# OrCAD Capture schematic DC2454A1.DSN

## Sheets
1 PAGE2: size Custom; title: POLY-PHASE DC/DC CONVERTER WITH POWER SYSTEM MANAGEMENT; rev: 1; company: TM
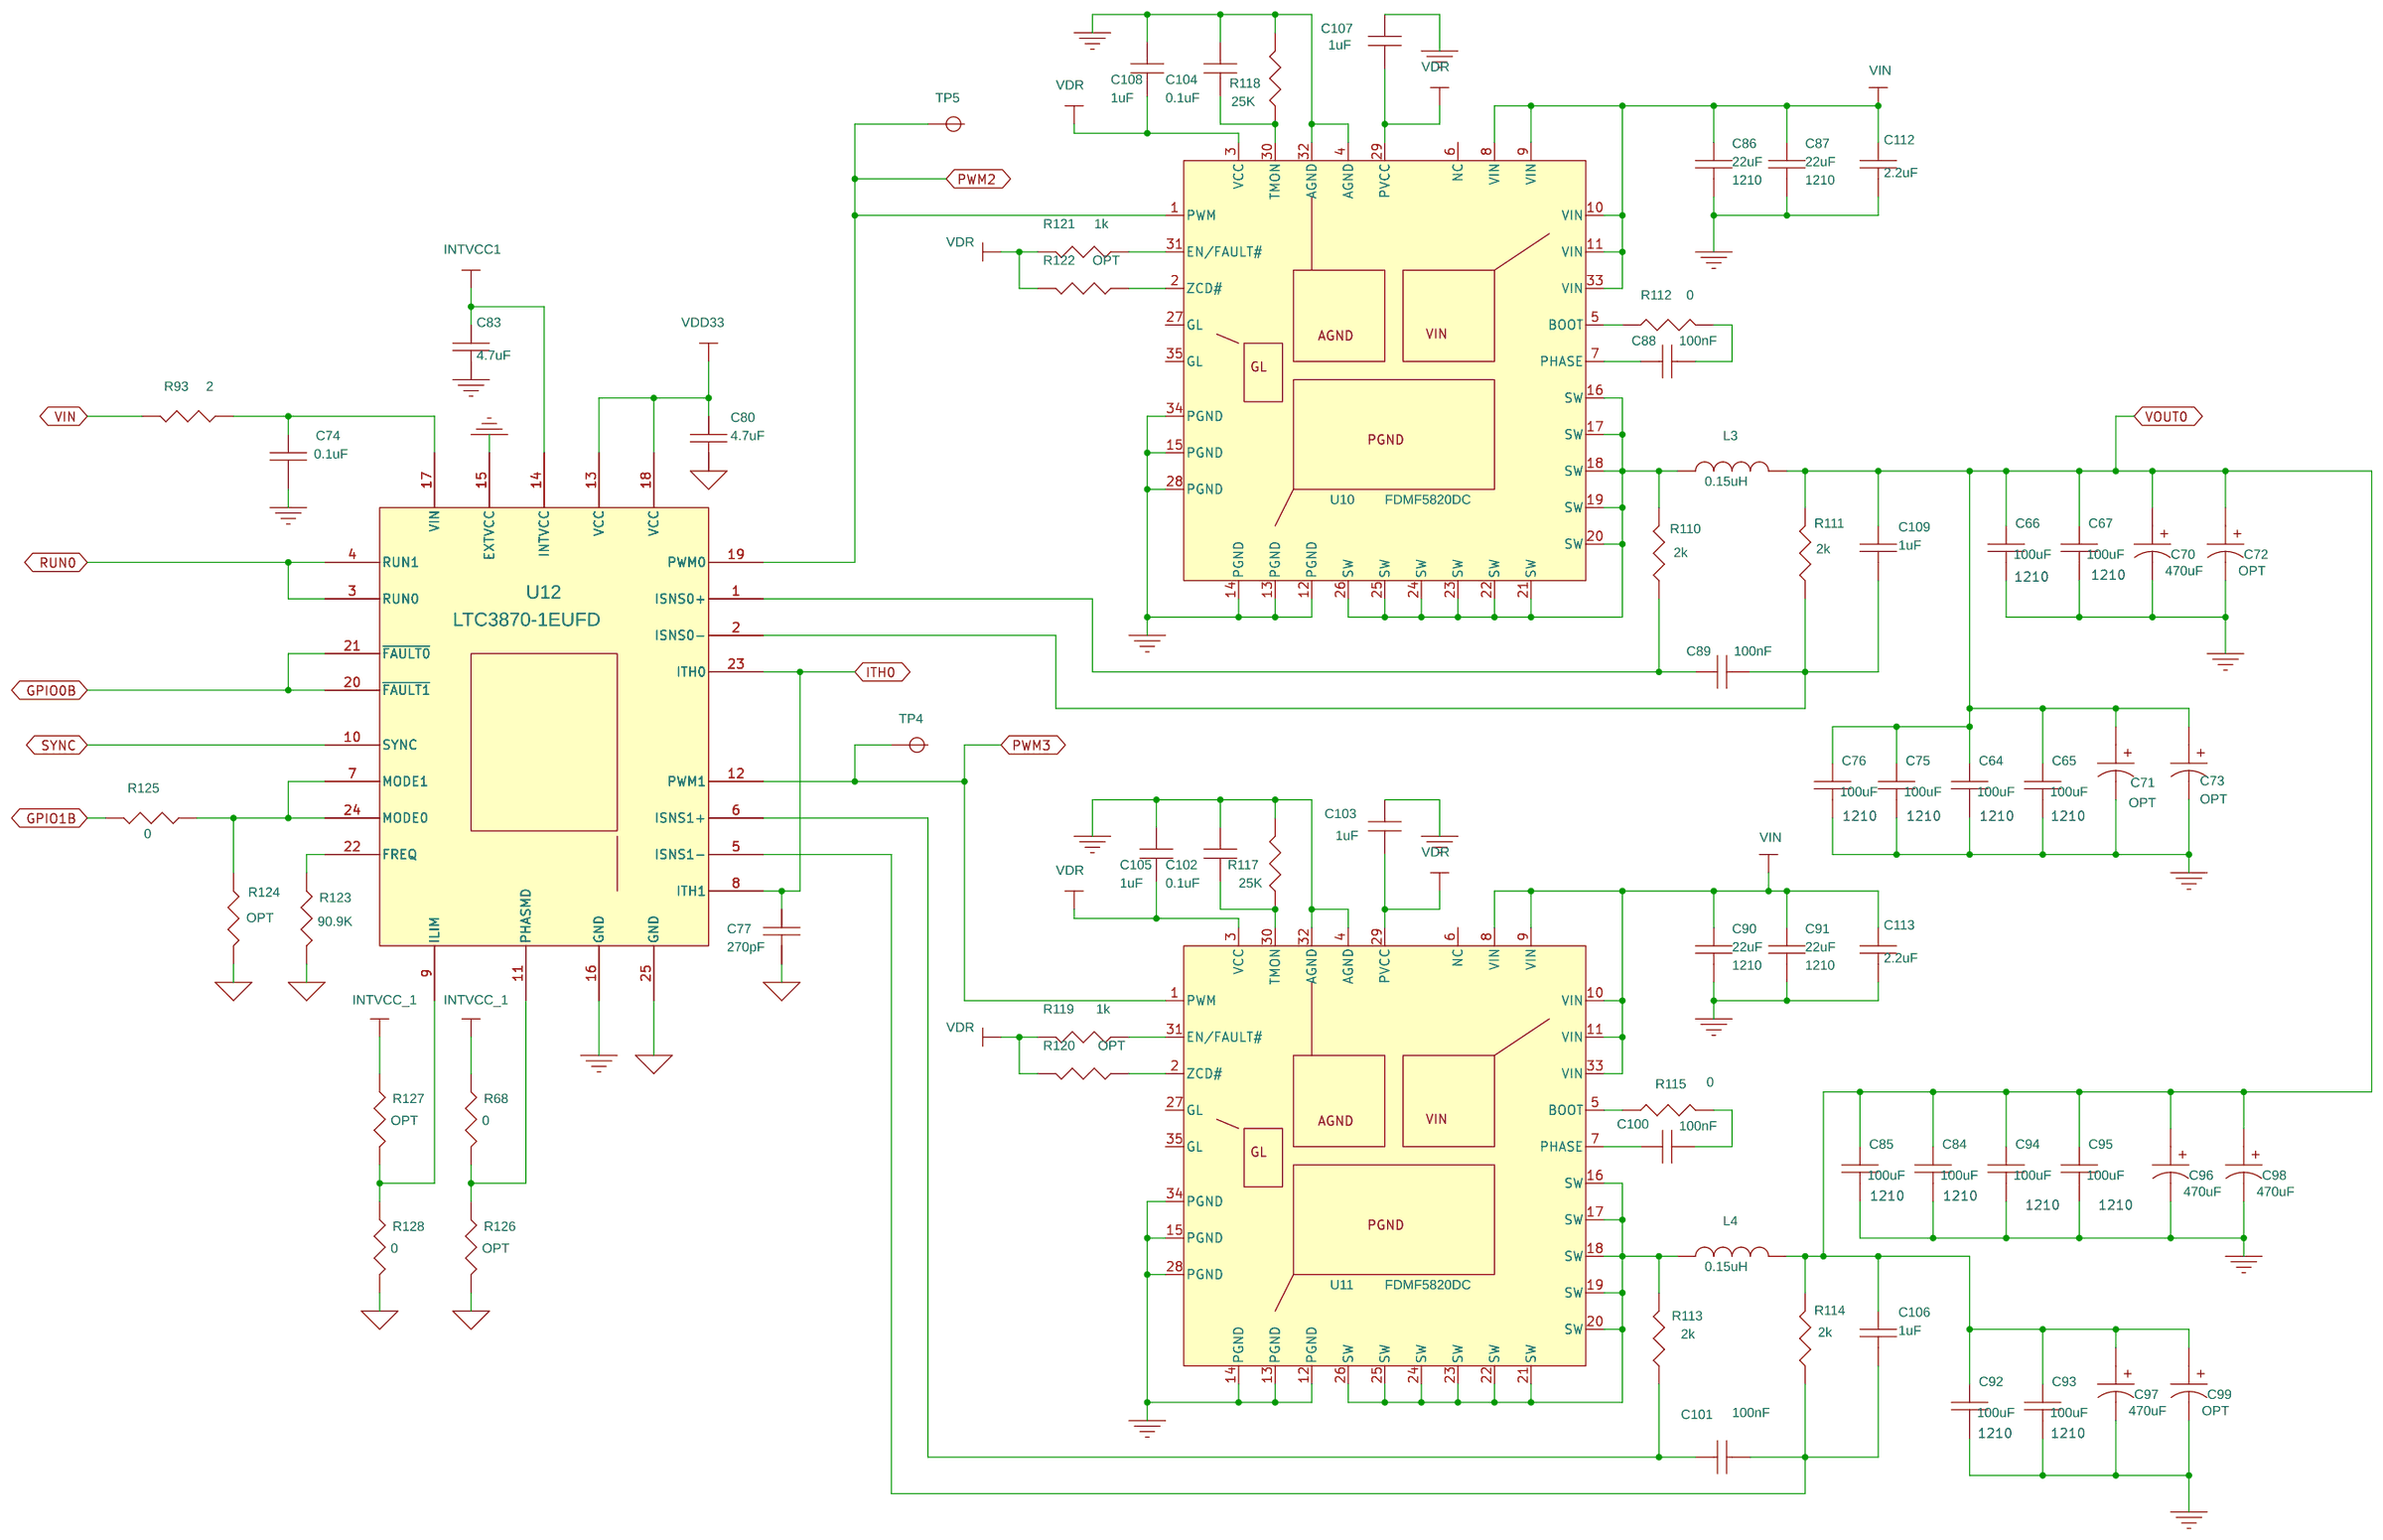
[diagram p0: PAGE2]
2 PAGE1: size Custom
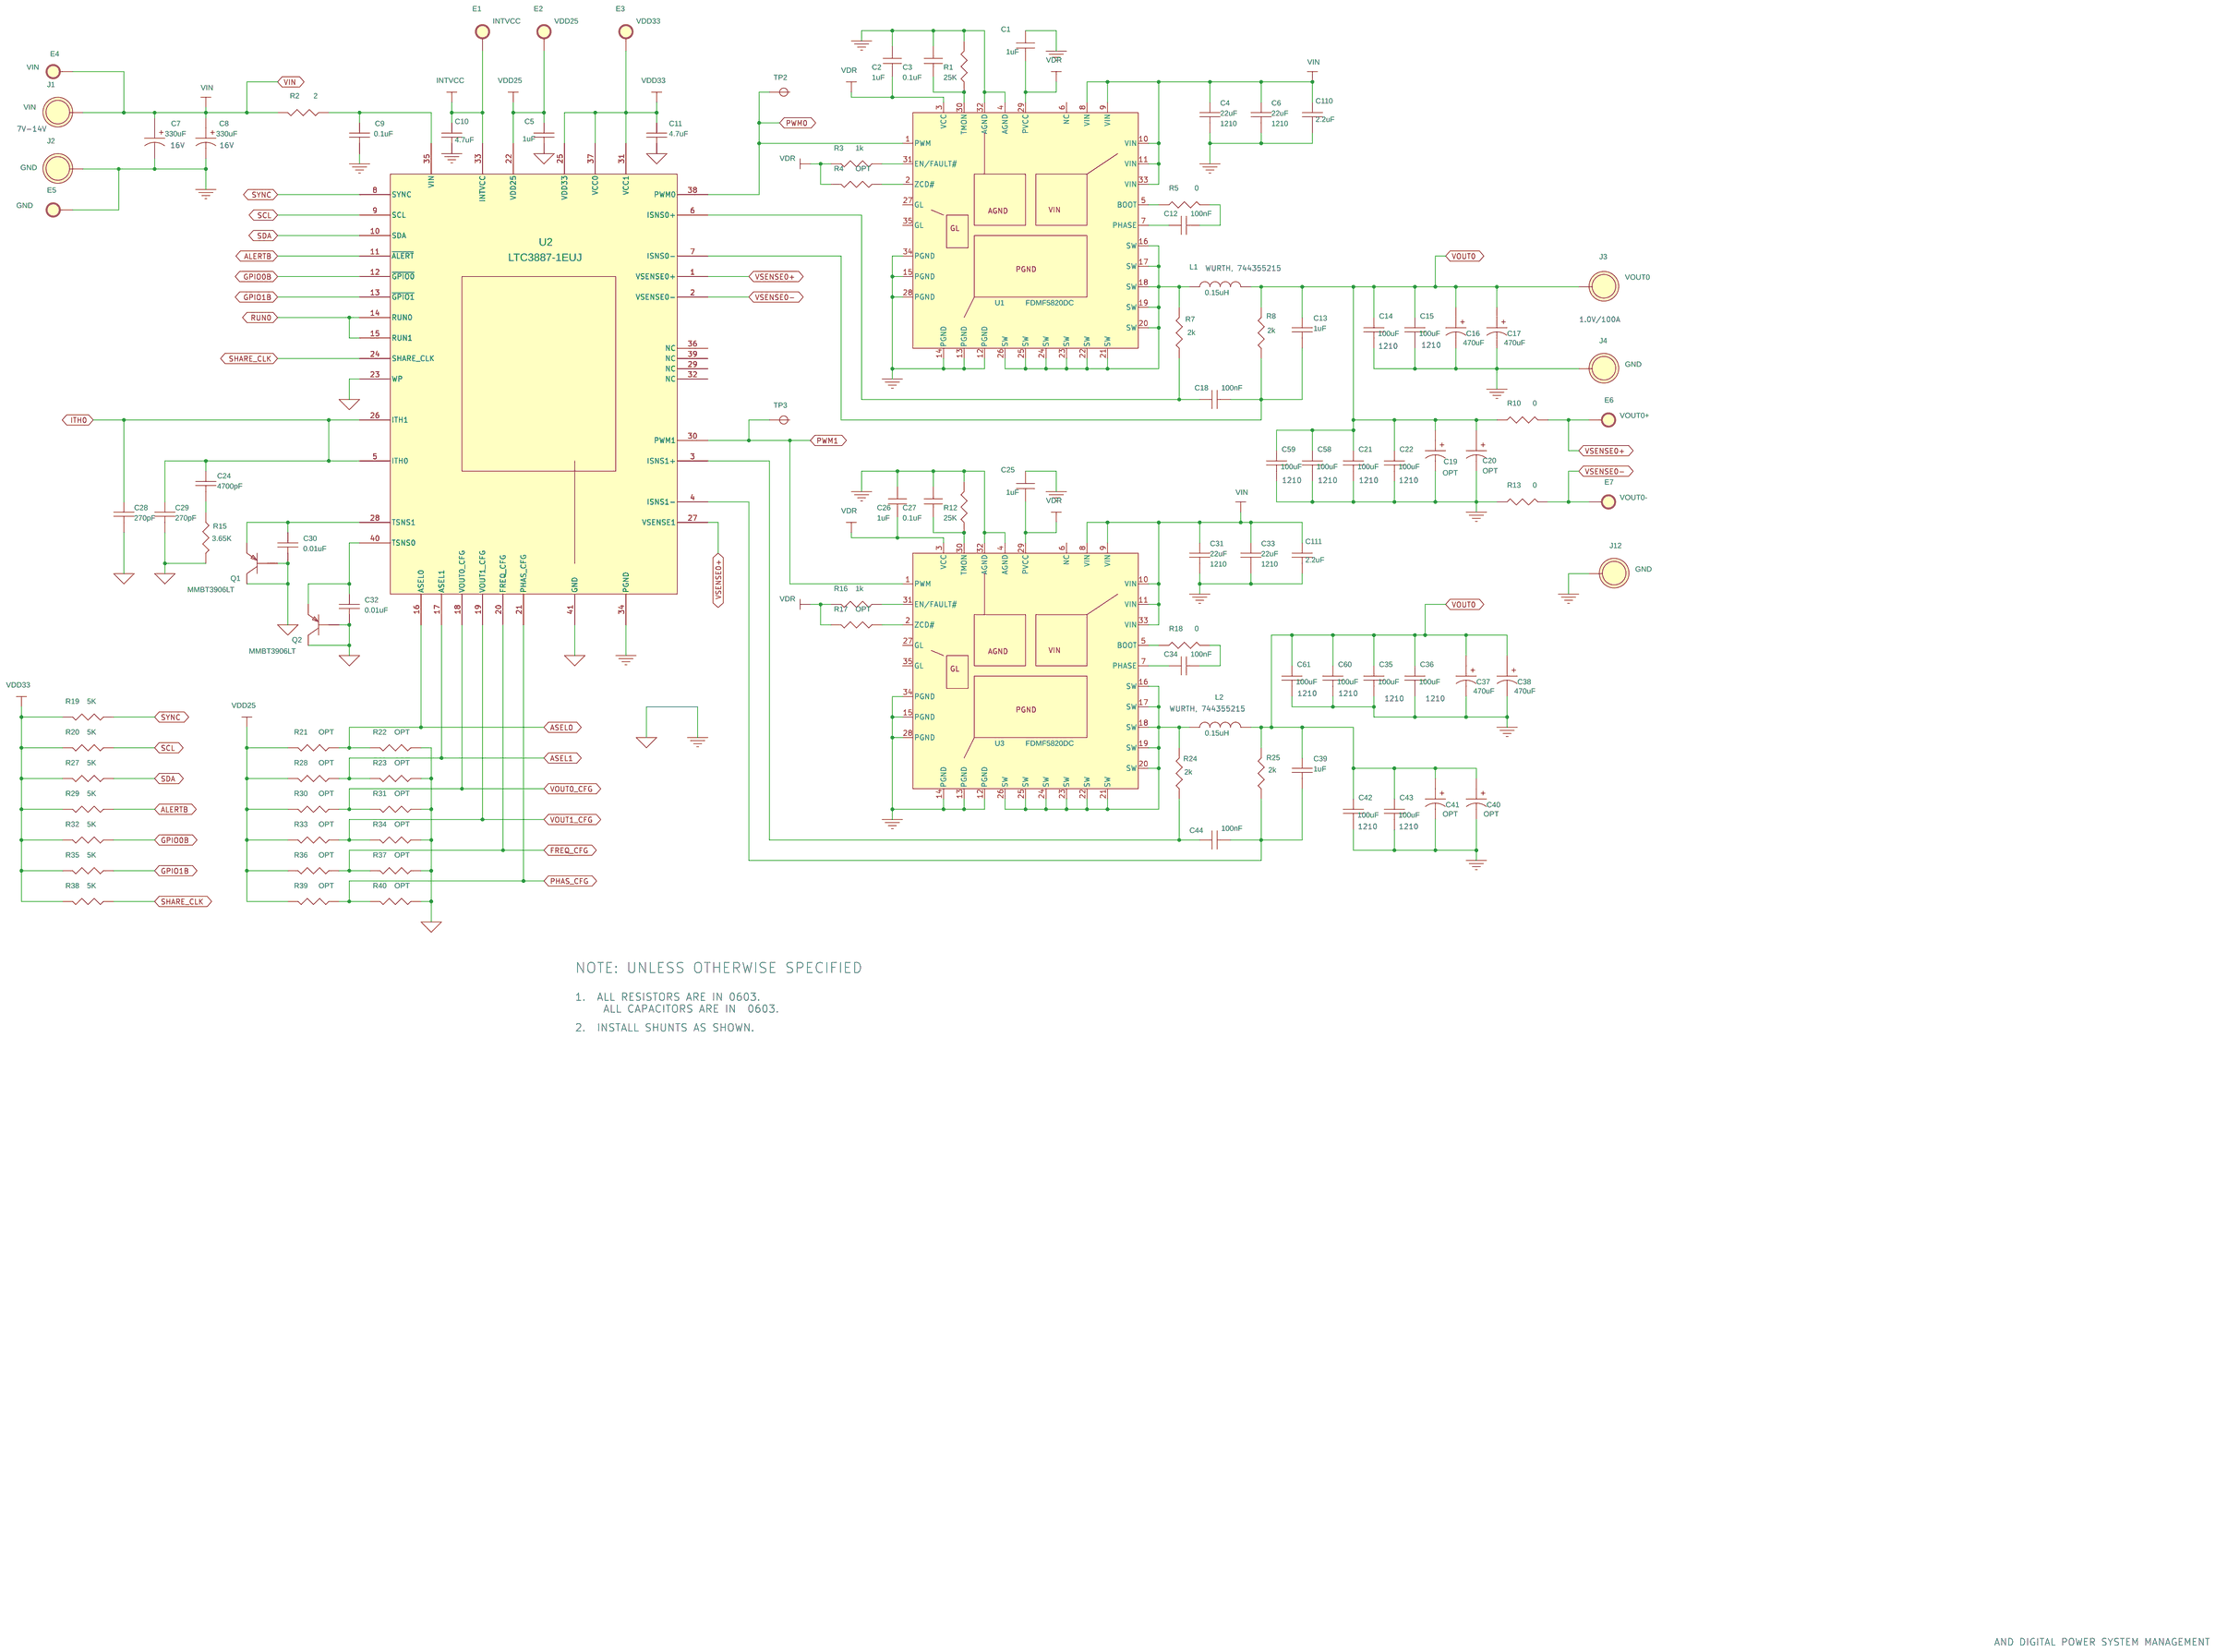
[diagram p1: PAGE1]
3 PAGE3: size Custom
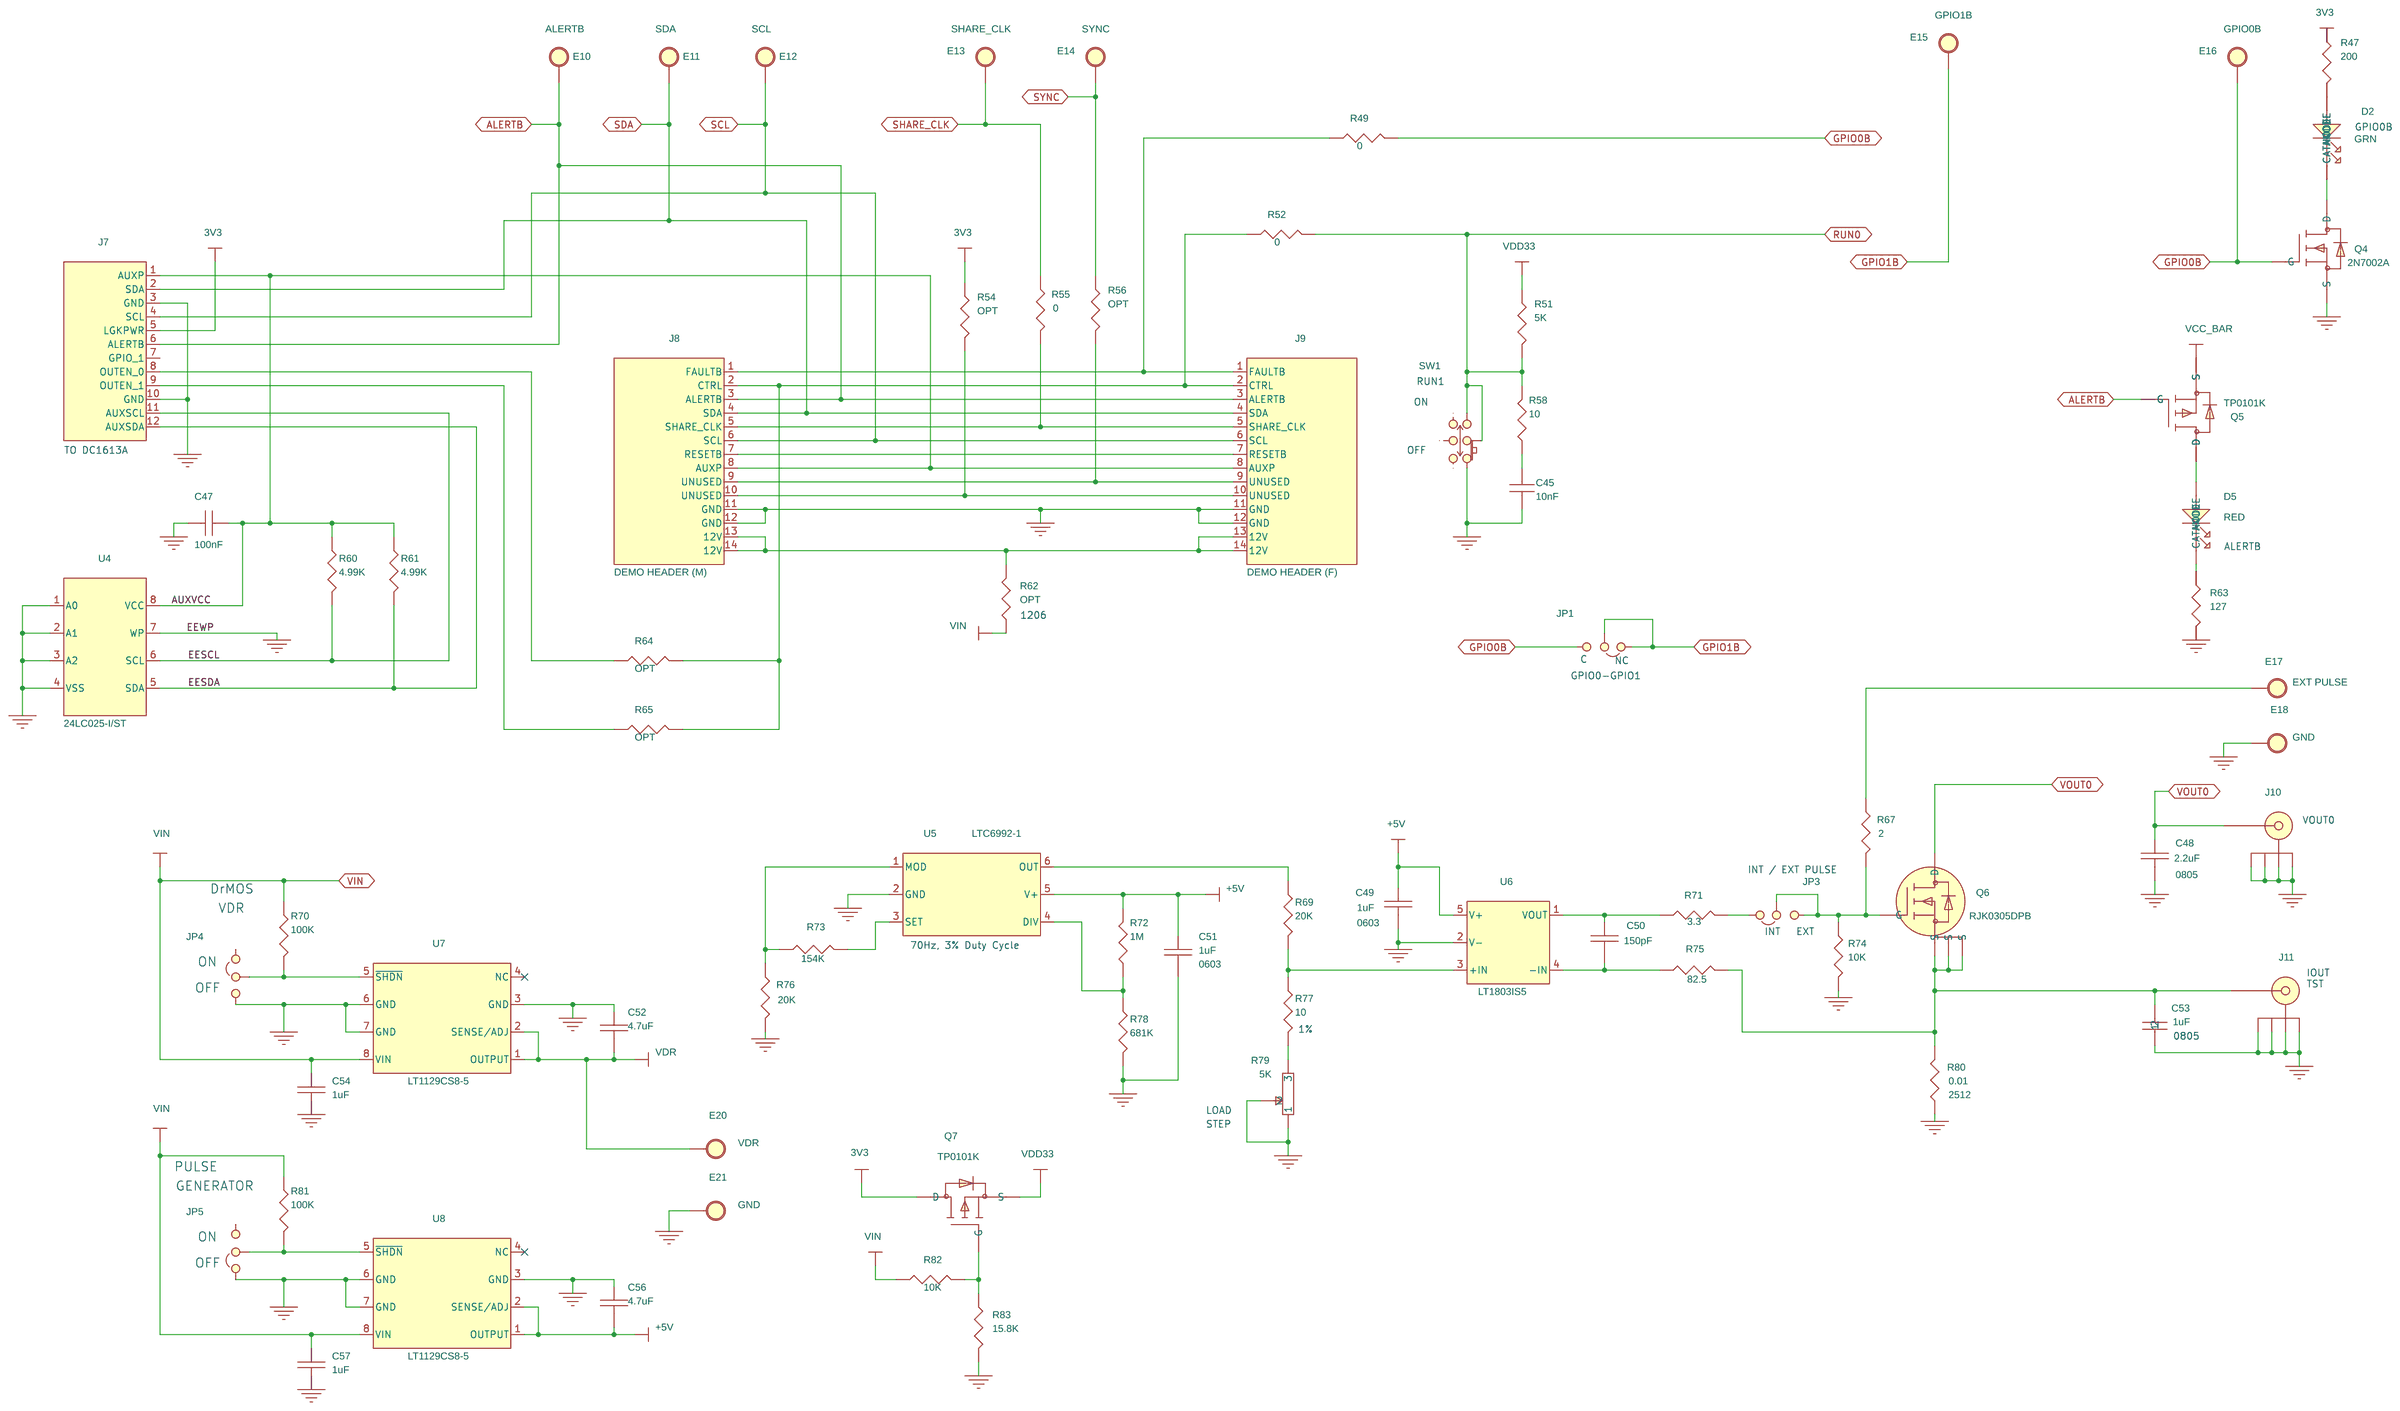
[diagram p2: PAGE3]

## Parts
sheet PAGE1
C1  1uF  [0402]
C2  1uF  [0402]
C3  0.1uF  [0402]
C4  22uF  [1210]
C5  1uF  [0603]
C6  22uF  [1210]
C7  330uF  [CAP_SANYO_F12]
C8  330uF  [CAP_SANYO_F12]
C9  0.1uF  [0603]
C10  4.7uF  [0603]
C11  4.7uF  [0603]
C12  100nF  [0402]
C13  1uF  [0603]
C14  100uF  [1210]
C15  100uF  [1210]
C16  470uF  [SANYO-C3-D2E(TPE)]
C17  470uF  [SANYO-C3-D2E(TPE)]
C18  100nF  [0603]
C19  OPT  [SANYO-C3-D2E(TPE)]
C20  OPT  [SANYO-C3-D2E(TPE)]
C21  100uF  [1210]
C22  100uF  [1210]
C24  4700pF  [0603]
C25  1uF  [0402]
C26  1uF  [0402]
C27  0.1uF  [0402]
C28  270pF  [0603]
C29  270pF  [0603]
C30  0.01uF  [0603]
C31  22uF  [1210]
C32  0.01uF  [0603]
C33  22uF  [1210]
C34  100nF  [0402]
C35  100uF  [1210]
C36  100uF  [1210]
C37  470uF  [SANYO-C3-D2E(TPE)]
C38  470uF  [SANYO-C3-D2E(TPE)]
C39  1uF  [0603]
C40  OPT  [SANYO-C3-D2E(TPE)]
C41  OPT  [SANYO-C3-D2E(TPE)]
C42  100uF  [1210]
C43  100uF  [1210]
C44  100nF  [0603]
C58  100uF  [1210]
C59  100uF  [1210]
C60  100uF  [1210]
C61  100uF  [1210]
C110  2.2uF  [0603]
C111  2.2uF  [0603]
E1  TURRETS  [TURRETS]
E2  TURRETS  [TURRETS]
E3  TURRETS  [TURRETS]
E4  TURRETS  [TURRETS]
E5  GND  [TURRETS]
E6  TURRETS  [TURRETS]
E7  TURRETS  [TURRETS]
J1  VIN  [KEY-575-4]
J2  GND  [KEY-575-4]
J3  VOUT0  [CON\LUG\10]
J4  GND  [CON\LUG\10]
J12  GND  [CON\LUG\10]
L1  0.15uH  [PA0515]
L2  0.15uH  [PA0515]
Q1  MMBT3906LT  [SOT-416]
Q2  MMBT3906LT  [SOT-416]
R1  25K  [0402]
R2  2  [0603]
R3  1k  [0402]
R4  OPT  [0402]
R5  0  [0402]
R7  2k  [0603]
R8  2k  [0603]
R10  0  [0603]
R12  25K  [0402]
R13  0  [0603]
R15  3.65K  [0603]
R16  1k  [0402]
R17  OPT  [0402]
R18  0  [0402]
R19  5K  [0603]
R20  5K  [0603]
R21  OPT  [0603]
R22  OPT  [0603]
R23  OPT  [0603]
R24  2k  [0603]
R25  2k  [0603]
R27  5K  [0603]
R28  OPT  [0603]
R29  5K  [0603]
R30  OPT  [0603]
R31  OPT  [0603]
R32  5K  [0603]
R33  OPT  [0603]
R34  OPT  [0603]
R35  5K  [0603]
R36  OPT  [0603]
R37  OPT  [0603]
R38  5K  [0603]
R39  OPT  [0603]
R40  OPT  [0603]
TP2  TURRETS  [PAD]
TP3  TURRETS  [PAD]
U1  DC/DC Converters  [FDMF5821DC]
U2  LTC3887-1EUJ  [UJ-40-QFN(6X6mm)]
U3  DC/DC Converters  [FDMF5821DC]
sheet PAGE2
C64  100uF  [1210]
C65  100uF  [1210]
C66  100uF  [1210]
C67  100uF  [1210]
C70  470uF  [SANYO-C3-D2E(TPE)]
C71  OPT  [SANYO-C3-D2E(TPE)]
C72  OPT  [SANYO-C3-D2E(TPE)]
C73  OPT  [SANYO-C3-D2E(TPE)]
C74  0.1uF  [0603]
C75  100uF  [1210]
C76  100uF  [1210]
C77  270pF  [0603]
C80  4.7uF  [0603]
C83  4.7uF  [0603]
C84  100uF  [1210]
C85  100uF  [1210]
C86  22uF  [1210]
C87  22uF  [1210]
C88  100nF  [0402]
C89  100nF  [0603]
C90  22uF  [1210]
C91  22uF  [1210]
C92  100uF  [1210]
C93  100uF  [1210]
C94  100uF  [1210]
C95  100uF  [1210]
C96  470uF  [SANYO-C3-D2E(TPE)]
C97  470uF  [SANYO-C3-D2E(TPE)]
C98  470uF  [SANYO-C3-D2E(TPE)]
C99  OPT  [SANYO-C3-D2E(TPE)]
C100  100nF  [0402]
C101  100nF  [0603]
C102  0.1uF  [0402]
C103  1uF  [0402]
C104  0.1uF  [0402]
C105  1uF  [0402]
C106  1uF  [0603]
C107  1uF  [0402]
C108  1uF  [0402]
C109  1uF  [0603]
C112  2.2uF  [0603]
C113  2.2uF  [0603]
L3  0.15uH  [PA0515]
L4  0.15uH  [PA0515]
R68  0  [0603]
R93  2  [0603]
R110  2k  [0603]
R111  2k  [0603]
R112  0  [0402]
R113  2k  [0603]
R114  2k  [0603]
R115  0  [0402]
R117  25K  [0402]
R118  25K  [0402]
R119  1k  [0402]
R120  OPT  [0402]
R121  1k  [0402]
R122  OPT  [0402]
R123  90.9K  [0603]
R124  OPT  [0603]
R125  0  [0603]
R126  OPT  [0603]
R127  OPT  [0603]
R128  0  [0603]
TP4  TURRETS  [PAD]
TP5  TURRETS  [PAD]
U10  DC/DC Converters  [FDMF5821DC]
U11  DC/DC Converters  [FDMF5821DC]
U12  LTC3870-1EUFD  [UF_24_4MMX4MM]
sheet PAGE3
C45  10nF  [0603]
C47  100nF  [0603]
C48  2.2uF  [0805]
C49  1uF  [0603]
C50  150pF  [0603]
C51  1uF  [0603]
C52  4.7uF  [1206]
C53  1uF  [0805]
C54  1uF  [1206]
C56  4.7uF  [0603]
C57  1uF  [1206]
D2  LED  [WURTH_LED]
D5  LED  [WURTH_LED]
E10  TURRETS  [TURRETS]
E11  TURRETS  [TURRETS]
E12  TURRETS  [TURRETS]
E13  TURRETS  [TURRETS]
E14  TURRETS  [TURRETS]
E15  TURRETS  [TURRETS]
E16  TURRETS  [TURRETS]
E17  TURRETS  [TURRETS]
E18  TURRETS  [TURRETS]
E20  TURRETS  [TURRETS]
E21  TURRETS  [TURRETS]
J7  HD2X6-079  [HD2X6-079-MOLEX]
J8  DEMO HEADER (M)  [NPPN072FJFN]
J9  DEMO HEADER (F)  [NPPN072FJFN-RC]
J10  CONNEX 112404  [BNC]
J11  CONNEX 112404  [BNC]
JP1  JP3X1/079\NO\12  [HD1X3-079]
JP3  JP3X1/079\NO\12  [HD1X3-079]
JP4  JP3X1/079\NO\12  [HD1X3-079]
JP5  JP3X1/079\NO\12  [HD1X3-079]
Q4  2N7002A  [SOT-23]
Q5  TP0101K  [SOT-23]
Q6  RJK0305DPB  [LFPAK]
Q7  TP0101K  [SOT-23]
R47  200  [0603]
R49  0  [0603]
R51  5K  [0603]
R52  0  [0603]
R54  OPT  [0603]
R55  0  [0603]
R56  OPT  [0603]
R58  10  [0603]
R60  4.99K  [0603]
R61  4.99K  [0603]
R62  OPT  [0603]
R63  127  [0603]
R64  OPT  [0603]
R65  OPT  [0603]
R67  2  [0603]
R69  20K  [0603]
R70  100K  [0603]
R71  3.3  [0603]
R72  1M  [0603]
R73  154K  [0603]
R74  10K  [0603]
R75  82.5  [0603]
R76  20K  [0603]
R77  10  [0603]
R78  681K  [0603]
R79  5K  [POTENTIOMETER/3386]
R80  0.01  [2512]
R81  100K  [0603]
R82  10K  [0603]
R83  15.8K  [0603]
SW1  JP3X1/079\NO\12  [JS202011]
U4  24LC025-I/ST  [TSSOP-8_4.4MM]
U5  LTC6992-1  [S6-TSOT23]
U6  LT1803IS5  [S5-TSOT23]
U7  LT1129CS8-5  [SO8NB]
U8  LT1129CS8-5  [SO8NB]

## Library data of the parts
C1 C25 C103 C107 = CAP-NP: CAP, 0603 2.2uF 10% 16V X5R; Grade: X5R; Voltage rating: 16V
C2 C3 C26 C27 C102 C104 C105 C108 = CAP-NP: CAP, 0603 2.2uF 10% 16V X5R; Grade: X5R; Part Number: C0603C225K4PAC; Voltage rating: 16V
C4 C6 C31 C33 C86 C87 C90 C91 = CAP1210_2: Component: cap; Manufacturer: Taiyo Yuden; Manufacturer P/N: GMK325BJ106KN-T; Tolerance: 10%; Type: cer 1210; Vendor: Digikey; Vendor P/N: 587-1439-1-ND; Volts/Amps/Watts: 35V
C5 C10 C83 C110-C113 = CAP_3: CAP, 0402 1uF 20% 10V X5R; Manufacturer: Taiyo Yuden; Manufacturer P/N: EMK107B7105KA-T; Part Number: TDK C1005X5R1A105M; Type: cer 0603 X7R; Vendor: Digikey; Vendor P/N: 587-1241-1-ND; Volts/Amps/Watts: 10V
C7 C8 = CAPR12X5_0: Component: cap; Manufacturer: SANYO; Manufacturer P/N: 16SVP330M; Tolerance: 20%; Type: OS-CON; Volts/Amps/Watts: 16V
C9 C74 = CAP_3: CAP, 0402 0.1uF 10% 16V X7R; Manufacturer: TDK; Manufacturer P/N: C1608X7R1H104K; Part Number: AVX 0402YC103KAT2A; Part Type: 0402; Tolerance: 10%; Type: cer 0603 X7R; Vendor: Digikey; Vendor P/N: 445-1314-1-ND; Volts/Amps/Watts: 16V
C11 C80 = CAP_3: CAP, 0402 1uF 20% 10V X5R; Manufacturer: Taiyo Yuden; Manufacturer P/N: EMK107B7105KA-T; Part Number: TDK C1005X5R1A105M; Part Type: 0402; Type: cer 0603 X7R; Vendor: Digikey; Vendor P/N: 587-1241-1-ND; Volts/Amps/Watts: 10V
C12 C18 C34 C44 C88 C89 C100 C101 = EMK107BJ224MA: CAP, 0603 0.22uF 10% 25V X5R
C13 C39 C106 C109 = CAP_3: CAP, 0805 47uF 20% 6.3V X5R; Component: cap; Manufacturer: TDK; Manufacturer P/N: C3225X5R0J107M; Part Number: TAIYO YUDEN JMK212BJ476MG-T; Part Type: CAP1210; Tolerance: 20%; Type: cer 1210 X5R; Vendor: Digikey; Vendor P/N: 445-1437-1-ND; Volts/Amps/Watts: 6.3v
C14 C15 C21 C22 C58-C61 C64-C67 C75 C76 C84 C85 = CAP_3: Component: cap; Manufacturer: TDK; Manufacturer P/N: C3225X5R0J107M; Part Type: CAP1210; Tolerance: 20%; Type: cer 1210 X5R; Vendor: Digikey; Vendor P/N: 445-1437-1-ND; Volts/Amps/Watts: 6.3v
C16 C17 C19 C20 C37 C38 C40 C41 C70-C73 C96-C99 = CAPR12X5_0: Component: cap; Manufacturer: SANYO; Manufacturer P/N: 6TPF330M9L; Tolerance: 20%; Type: TANT; Volts/Amps/Watts: 6.3V
C24 = CAP_3: CAP, 0402 1000pF 10% 25V X7R; Component: cap; Manufacturer: TDK; Manufacturer P/N: C1608C0G1H102J; Part Number: AVX 04023C102KAT2A; Tolerance: 5%; Type: cer 0603; Vendor: Digikey; Vendor P/N: 445-1293-1-ND; Volts/Amps/Watts: 50V
C28 C29 C77 = CAP_3: CAP, 0402 47pF 10% 50V NPO; Component: cap; Manufacturer: TDK; Manufacturer P/N: C1608C0G1H101J; Part Number: AVX 04025A470KAT; Tolerance: 5%; Type: cer 0603; Vendor: Digikey; Vendor P/N: 445-1281-1-ND
C30 C32 = CAP0603_1: CAP, 0402 0.1uF 10% 16V X7R; Component: cap; Manufacturer: TDK; Manufacturer P/N: C1608X7R1H103K; Part Number: AVX 0402YC103KAT2A; Part Type: 0402; Tolerance: 10%; Type: cer 0603; Vendor: Digikey; Vendor P/N: 445-1311-1-ND; Volts/Amps/Watts: 50V
C35 C36 C42 C43 C92-C95 = CAP_3: Component: cap; Manufacturer: TDK; Manufacturer P/N: C3225X5R0J107M; Tolerance: 20%; Type: cer 1210 X5R; Vendor: Digikey; Vendor P/N: 445-1437-1-ND; Volts/Amps/Watts: 6.3v
E1 = TURRETS_2: Label: INTVCC; Vendor: Digikey; Vendor P/N: 1593-2K-ND
E2 = TURRETS_2: Label: VDD25; Vendor: Digikey; Vendor P/N: 1593-2K-ND
E3 = TURRETS_2: Label: VDD33; Vendor: Digikey; Vendor P/N: 1593-2K-ND
E4 = TURRETS_2: Label: VIN; Manufacturer: Keystone; Manufacturer P/N: 1593-2; Vendor: Digikey; Vendor P/N: 1593-2K-ND
E5 = TURRETS_2: Manufacturer: Keystone; Manufacturer P/N: 1593-2; Vendor: Digikey; Vendor P/N: 1593-2K-ND
E6 = TURRETS_2: Label: VOUT0+; Vendor: Digikey; Vendor P/N: 1593-2K-ND
E7 = TURRETS_2: Label: VOUT0-; Vendor: Digikey; Vendor P/N: 1593-2K-ND
J1 = E_4: STATUS: 1.6V, 1.8V, 2.0V OR 2.5V @ 15A
J2 J4 J12 = E_4: STATUS: 1.6V, 1.8V, 2.0V OR 2.5V @ 15A; VALUE2: J1
J3 = E_4: VALUE2: 1V@80A
L1-L4 = 744355147_Wurth: 4th Part Field: WURTH EL.; 5th Part Field: DELTA
Q1 Q2 = MMBT3906LT1_0: XSTR, PNP SMALL SIGNAL; Component: trans; Manufacturer P/N: MMBT3906LT1G; Part Number: ON SEMI MMBT3906TTI; Part Type: MMBT3906LT1; Vendor P/N: MMBT3906LT1GOSCT-ND
R1 R12 R117 R118 = CJ06-000M: RES, 0603 0 OHM JUMPER
R2 R93 R123-R125 = RES0603_9: RES, 0402 2 OHMS 1% 1/16W; Manufacturer: Panasonic; Part Number: VISHAY CRCW04022R00FNEA; Part Type: 0402; Vendor: Digikey; Vendor P/N: P100HCT-ND; Volts/Amps/Watts: 0.1W
R3 R4 R16 R17 R119-R122 = RES0603_9: Manufacturer: Panasonic; Manufacturer P/N: ERJ-3EKF2002V; Vendor: Digikey; Vendor P/N: P20.0KHCT-ND; Volts/Amps/Watts: 0.1W
R5 R7 R8 R10 R13 R18 R24 R25 R110-R115 = CJ06-000M: RES, 0603 0 OHM JUMPER; Part Number: YAGEO RC0603FR-070RL
R15 R68 R126-R128 = RES0603_9: RES, 0402 4.53k OHMS 1% 1/16W; Component: res; Label: <label>; Manufacturer: Panasonic; Manufacturer P/N: ERJ-3EKF5901V; Part Number: VISHAY CRCW04024K53FKED; Tolerance: 1%; Vendor: Digikey; Vendor P/N: P5.90KHCT-ND; Volts/Amps/Watts: 0.1W
R19 R20 R27 R29 R32 R35 R38 = RES0603_9: RES, 0402 5k OHMS 5% 1/16W; Manufacturer: Panasonic; Manufacturer P/N: ERJ-3EKF2002V; Part Number: VISHAY CRCW04025K00JNED; Vendor: Digikey; Vendor P/N: P20.0KHCT-ND; Volts/Amps/Watts: 0.1W
R21-R23 R28 R30 R31 R33 R34 R36 R37 R39 R40 = RES0603_9: RES, 0603 OPTION; Manufacturer: Panasonic; Manufacturer P/N: ERJ-3EKF2002V; Part Number: OPTION; Vendor: Digikey; Vendor P/N: P20.0KHCT-ND; Volts/Amps/Watts: 0.1W
TP2-TP5 = PAD_2: Component: tp; Label: <Label>; Vendor: Digikey; Vendor P/N: 1593-2K-ND
U1 U3 U10 U11 = R2J20602NP(Renesas)_5: 5th Part Field: FDMF5820DC
U2 = LTC3880-M0001_15: IC,; Component: IC; Manufacturer: LTC; Manufacturer P/N: LTC3880_M0001; Part Number: LINEAR TECH LTC3880EUJ; Part Type: LTC3880EUF; Vendor: LTC; Vendor P/N: LTC3880_M0001
U12 = LTC3880-M0001_17: Component: IC; Manufacturer: LTC; Manufacturer P/N: LTC3880_M0001; Vendor: LTC; Vendor P/N: LTC3880_M0001
C45 = CAP_NP: CAP, 0603 10nF 10% 25V X7R; Part Number: AVX 06033C103KAT2A
C47 = CAP_NP: CAP, 0603 100nF 20% 16V X7R; Part Number: AVX 0603YC104MAT2A
C48 = CAP1206_1: Manufacturer: Kemet; Manufacturer P/N: C1206C106K8RACTU; Tolerance: 10%; Type: cer 1206 X7R; Vendor: Digikey; Vendor P/N: 399-4937-1-ND; Volts/Amps/Watts: 10V
C49 C51 C54 C57 = CAP1206_1: Manufacturer: AVX; Manufacturer P/N: 12063C105KAT2A; Tolerance: 10%; Type: cer 1206 X7R; Vendor: Digikey; Vendor P/N: 478-1567-1-ND; Volts/Amps/Watts: 25V
C50 = CAP0603_2: Component: cap; Manufacturer: TDK; Manufacturer P/N: C1608C0G1H102J; Tolerance: 5%; Type: cer 0603; Vendor: Digikey
C52 C56 = CAP1206_1: Manufacturer: AVX; Tolerance: 10%; Type: cer 1206 X7R; Vendor: Digikey; Vendor P/N: 478-1567-1-ND; Volts/Amps/Watts: 25V
C53 = CAP_NP_1: CAP, 0603 1.5nF 10% 50V X7R; Part Number: AVX 06033C152KAT
D2 = LED_1: 1%: GRN
D5 = LED_1: 1%: RED
E10 = TURRETS_2: Label: ALERTB; Manufacturer: Keystone; Manufacturer P/N: 1593-2; Vendor: Digikey; Vendor P/N: 1593-2K-ND
E11 = TURRETS_2: Label: SDA; Manufacturer: Keystone; Manufacturer P/N: 1593-2; Vendor: Digikey; Vendor P/N: 1593-2K-ND
E12 = TURRETS_2: Label: SCL; Manufacturer: Keystone; Manufacturer P/N: 1593-2; Vendor: Digikey; Vendor P/N: 1593-2K-ND
E13 = TURRETS_2: Label: SHARE_CLK; Manufacturer: Keystone; Manufacturer P/N: 1593-2; Vendor: Digikey; Vendor P/N: 1593-2K-ND
E14 = TURRETS_2: Label: SYNC; Manufacturer: Keystone; Manufacturer P/N: 1593-2; Vendor: Digikey; Vendor P/N: 1593-2K-ND
E15 = TURRETS_2: Label: GPIO1B; Manufacturer: Keystone; Manufacturer P/N: 1593-2; Vendor: Digikey; Vendor P/N: 1593-2K-ND
E16 = TURRETS_2: Label: GPIO0B; Manufacturer: Keystone; Manufacturer P/N: 1593-2; Vendor: Digikey; Vendor P/N: 1593-2K-ND
E17 = TURRETS_2: Label: EXT PULSE; Manufacturer: Keystone; Manufacturer P/N: 1593-2; Vendor: Digikey; Vendor P/N: 1593-2K-ND
E18 E21 = TURRETS_2: Label: GND; Manufacturer: Keystone; Manufacturer P/N: 1593-2; Vendor: Digikey; Vendor P/N: 1593-2K-ND
E20 = TURRETS_2: Label: VDR; Manufacturer: Keystone; Manufacturer P/N: 1593-2; Vendor: Digikey; Vendor P/N: 1593-2K-ND
J7 = HD2X6-079-PMBUS_2: HEADER, 12PIN 2mm STR DL; Label: DC1427A HEADER; Manufacturer: MOLEX; Manufacturer P/N: 87831-1220; Part Number: FCI 98414-G06-12ULF; Type: header 12POS 2MM VERT; Vendor: Digikey; Vendor P/N: WM18561-ND
J8 = PMBUS_HEADER20_3: HEADER, 20PIN DUAL ROW R/A; Component: con; Manufacturer: Mill Max; Manufacturer P/N: 802-40-020-20-0001; Part Number: MILL MAX 802-40-020-20-0001; Part Type: HDR_2X10_RA_REV; Type: header RA 20 dual row; Vendor: LTC; Vendor P/N: 802-40-020-20-001
J9 = PMBUS_CONNECTOR20_3: CONN, SOCKET 20PIN  DUAL ROW R/A; Component: con; Manufacturer: Mill Max; Manufacturer P/N: 803-93-020-20-001; Part Number: MILL MAX 803-93-020-20-001; Part Type: HDR2X10RA; Type: conn  RA 20 dual row; Vendor: LTC; Vendor P/N: 803-93-020-20-001
J10 J11 = BNC5-SCH_0: CONN,BNC,5 PINS
JP1 JP3 JP5 = JP3X1_079_NO_12_2
JP4 = JP3X1_079_NO_12_1
Q4 = TRANSISTOR_0: XSTR, N-CHANNEL DMOS FET
Q5 Q7 = P-MOSFET: XSTR, N-CHANNEL DMOS FET
Q6 = MOS_FET_5: XSTR, N-CHANNEL DMOS FET
R47 R63 = RES0603_9: Label: OPT 0; Manufacturer: Rohm; Manufacturer P/N: RHM0.0GCT-ND; Tolerance: 5%; Vendor: Digikey; Vendor P/N: RHM0.0GCT-ND; Volts/Amps/Watts: 0.1W
R49 R52 = RES0603_0: RES, 0603 0 OHMS JUMPER; Label: OPT 0; Manufacturer: Rohm; Manufacturer P/N: RHM0.0GCT-ND; Part Number: VISHAY CRCW06030000Z0EA; Tolerance: 5%; Vendor: Digikey; Vendor P/N: RHM0.0GCT-ND; Volts/Amps/Watts: 0.1W
R51 R54 R56 R65 = RES0603_0: RES, 0603 OPTION; Label: OPT 0; Manufacturer: Rohm; Manufacturer P/N: RHM0.0GCT-ND; Part Number: OPTION; Tolerance: 5%; Vendor: Digikey; Vendor P/N: RHM0.0GCT-ND; Volts/Amps/Watts: 0.1W
R55 = RES0603_0: RES, 0603 0 OHMS JUMPER; Manufacturer: Rohm; Manufacturer P/N: RHM0.0GCT-ND; Part Number: VISHAY CRCW06030000Z0EA; Tolerance: 5%; Vendor: Digikey; Vendor P/N: RHM0.0GCT-ND; Volts/Amps/Watts: 0.1W
R58 = RES0603_1: RES, 0603 10 OHMS 5% 1/10W; Manufacturer: Rohm; Manufacturer P/N: RHM0.0GCT-ND; Part Number: VISHAY CRCW060310R0JNEA; Tolerance: 5%; Vendor: Digikey; Vendor P/N: RHM0.0GCT-ND; Volts/Amps/Watts: 0.1W
R60 R61 = RES0603_0: RES, 0603 4.99K OHMS 1% 1/10W; Manufacturer: ROHM; Manufacturer P/N: MCR03EZPFX4991; Part Number: VISHAY CRCW06034K99FKEA; Vendor: Digikey; Vendor P/N: RHM4.99KHCT-ND; Volts/Amps/Watts: 0.1w
R62 R64 = RES0603_3: RES, 0603 OPTION; Label: OPT 0; Manufacturer: Rohm; Manufacturer P/N: RHM0.0GCT-ND; Part Number: OPTION; Tolerance: 5%; Vendor: Digikey; Vendor P/N: RHM0.0GCT-ND; Volts/Amps/Watts: 0.1W
R67 R69 R71-R78 = RES0603_9: Manufacturer: ROHM; Manufacturer P/N: MCR03EZPFX4991; Vendor: Digikey; Vendor P/N: RHM4.99KHCT-ND; Volts/Amps/Watts: 0.1w
R70 R81 = RES0603_11
R79 = POT_A_0
R80 = RES0603_5: Label: 1W; Manufacturer: VISHAY; Manufacturer P/N: CRCW251230R0JNEG; Tolerance: 5%; Vendor: Digikey; Vendor P/N: 541-30XCT-ND; Volts/Amps/Watts: 0.1W
R82 = RES0603_9: Manufacturer: ROHM; Manufacturer P/N: MCR03EZPFX1002; Vendor: Digikey; Vendor P/N: RHM10.0KHCT-ND; Volts/Amps/Watts: 0.1W
R83 = RES0603_9
SW1 = JP3X1_079_NO_12_3: SWITCH, SUBMINATURE SLIDE; Part Number: C&K JS202011CQN
U4 = 24LC025-I_SN: IC, 24LC05-I/ST; Part Number: MICROCHIP 24LC025-I/ST
U5 = LT1129CS8-3_0.3
U6 = LT1129CS8-3_3.3
U7 U8 = LT1129CS8-3.3

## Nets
3V3: J7.5(LGKPWR) Q5.2(S) Q7.3(D) R47.1 R54.1
+5V: C49.1 C51.1 C56.2 R72.2 U5.5(V+) U6.5(V+) U8.1(OUTPUT) U8.2(SENSE/ADJ)
GND_POWER: C1.1 C2.1 C3.1 C4.2 C6.2 C7.2 C8.2 C9.2 C10.2 C14.2 C15.2 C16.2 C17.2 C19.2 C20.2 C21.2 C22.2 C25.1 C26.1 C27.1 C31.2 C33.2 C35.2 C36.2 C37.2 C38.2 C40.2 C41.2 C42.2 C43.2 C45.2 C47.2 C48.2 C49.2 C51.2 C52.1 C53.1 C54.2 C56.1 C57.2 C58.2 C59.2 C60.2 C61.2 C64.2 C65.2 C66.2 C67.2 C70.2 C71.2 C72.2 C73.2 C74.2 C75.2 C76.2 C83.2 C84.2 C85.2 C86.2 C87.2 C90.2 C91.2 C92.2 C93.2 C94.2 C95.2 C96.2 C97.2 C98.2 C99.2 C102.1 C103.1 C104.1 C105.1 C107.1 C108.1 C110.2 C111.2 C112.2 C113.2 E5.1(TP) E18.1(TP) E21.1(TP) J2.1(A) J4.1(A) J7.3(GND) J7.10(GND) J8.11(GND) J8.12(GND) J9.11(GND) J9.12(GND) J10.2 J10.3 J10.4 J10.5 J11.2 J11.3 J11.4 J11.5 J12.1(A) JP4.1 JP5.1 Q4.2(S) R1.1 R12.1 R13.2 R63.2 R74.2 R76.2 R78.2 R79.1 R79.2 R80.1 R83.2 R117.1 R118.1 SW1.3 U1.4(AGND) U1.12(PGND) U1.13(PGND) U1.14(PGND) U1.15(PGND) U1.28(PGND) U1.32(AGND) U1.34(PGND) U2.34(PGND) U3.4(AGND) U3.12(PGND) U3.13(PGND) U3.14(PGND) U3.15(PGND) U3.28(PGND) U3.32(AGND) U3.34(PGND) U4.1(A0) U4.2(A1) U4.3(A2) U4.4(VSS) U4.7(WP) U5.2(GND) U6.2(V-) U7.3(GND) U7.6(GND) U7.7(GND) U8.3(GND) U8.6(GND) U8.7(GND) U10.4(AGND) U10.12(PGND) U10.13(PGND) U10.14(PGND) U10.15(PGND) U10.28(PGND) U10.32(AGND) U10.34(PGND) U11.4(AGND) U11.12(PGND) U11.13(PGND) U11.14(PGND) U11.15(PGND) U11.28(PGND) U11.32(AGND) U11.34(PGND) U12.15(EXTVCC) U12.16(GND)
GND_SIGNAL: C5.2 C11.2 C28.2 C29.2 C30.2 C32.2 C77.2 C80.2 Q1.1(BASE) Q1.3(COLLECTOR) Q2.1(BASE) Q2.3(COLLECTOR) R15.2 R22.1 R23.1 R31.1 R34.1 R37.1 R40.1 R123.1 R124.1 R126.2 R128.2 U2.23(WP) U2.41(GND) U12.25(GND)
VDD25: C5.1 E2.1(TP) R21.2 R28.2 R30.2 R33.2 R36.2 R39.2 U2.22(VDD25)
VDD33: C11.1 C80.1 E3.1(TP) Q7.2(S) R19.2 R20.2 R27.2 R29.2 R32.2 R35.2 R38.2 R51.1 U2.25(VDD33) U2.31(VCC1) U2.37(VCC0) U12.13(VCC) U12.18(VCC)
VIN: C4.1 C6.1 C7.1 C8.1 C31.1 C33.1 C54.1 C57.1 C86.1 C87.1 C90.1 C91.1 C110.1 C111.1 C112.1 C113.1 E4.1(TP) J1.1(A) R2.1 R62.1 R70.1 R81.1 R82.1 R93.1 U1.8(VIN) U1.9(VIN) U1.10(VIN) U1.11(VIN) U1.33(VIN) U3.8(VIN) U3.9(VIN) U3.10(VIN) U3.11(VIN) U3.33(VIN) U7.8(VIN) U8.8(VIN) U10.8(VIN) U10.9(VIN) U10.10(VIN) U10.11(VIN) U10.33(VIN) U11.8(VIN) U11.9(VIN) U11.10(VIN) U11.11(VIN) U11.33(VIN)
ALERTB: E10.1(TP) J7.6(ALERTB) J8.3(ALERTB) J9.3(ALERTB) Q5.1(G) R29.1 U2.11(~{ALERT})
ASEL0: R21.1 R22.2 U2.16(ASEL0)
ASEL1: R23.2 R28.1 U2.17(ASEL1)
AUXVCC: C47.1 J7.1(AUXP) J8.8(AUXP) J9.8(AUXP) R60.1 R61.1 U4.8(VCC)
EESCL: J7.11(AUXSCL) R60.2 U4.6(SCL)
EESDA: J7.12(AUXSDA) R61.2 U4.5(SDA)
FREQ_CFG: R36.1 R37.2 U2.20(FREQ_CFG)
GPIO0B: E16.1(TP) JP1.3 Q4.1(G) R32.1 R49.2 U2.12(~{GPIO0}) U12.20(~{FAULT1}) U12.21(~{FAULT0})
GPIO1B: E15.1(TP) JP1.1 JP1.2 R35.1 R125.1 U2.13(~{GPIO1})
INTVCC: C10.1 E1.1(TP) U2.33(INTVCC)
INTVCC1: C83.1 U12.14(INTVCC)
INTVCC_1: R68.1 R127.1
ITH0: C24.1 C28.1 C29.1 C77.1 U2.5(ITH0) U2.26(ITH1) U12.8(ITH1) U12.23(ITH0)
PHAS_CFG: R39.1 R40.2 U2.21(PHAS_CFG)
PWM0: TP2.1(TP) U1.1(PWM) U2.38(PWM0)
PWM1: TP3.1(TP) U2.30(PWM1) U3.1(PWM)
PWM2: TP5.1(TP) U10.1(PWM) U12.19(PWM0)
PWM3: TP4.1(TP) U11.1(PWM) U12.12(PWM1)
RUN0: R51.2 R52.2 R58.2 SW1.1 SW1.2 U2.14(RUN0) U2.15(RUN1) U12.3(RUN0) U12.4(RUN1)
SCL: E12.1(TP) J7.4(SCL) J8.6(SCL) J9.6(SCL) R20.1 U2.9(SCL)
SDA: E11.1(TP) J7.2(SDA) J8.4(SDA) J9.4(SDA) R27.1 U2.10(SDA)
SHARE_CLK: E13.1(TP) R38.1 R55.1 U2.24(SHARE_CLK)
SYNC: E14.1(TP) R19.1 R56.1 U2.8(SYNC) U12.10(SYNC)
VDR: C1.2 C2.2 C25.2 C26.2 C52.2 C103.2 C105.2 C107.2 C108.2 E20.1(TP) R3.2 R4.2 R16.2 R17.2 R119.2 R120.2 R121.2 R122.2 U1.3(VCC) U1.29(PVCC) U3.3(VCC) U3.29(PVCC) U7.1(OUTPUT) U7.2(SENSE/ADJ) U10.3(VCC) U10.29(PVCC) U11.3(VCC) U11.29(PVCC)
VOUT0: C13.1 C14.1 C15.1 C16.1 C17.1 C19.1 C20.1 C21.1 C22.1 C35.1 C36.1 C37.1 C38.1 C39.1 C40.1 C41.1 C42.1 C43.1 C48.1 C58.1 C59.1 C60.1 C61.1 C64.1 C65.1 C66.1 C67.1 C70.1 C71.1 C72.1 C73.1 C75.1 C76.1 C84.1 C85.1 C92.1 C93.1 C94.1 C95.1 C96.1 C97.1 C98.1 C99.1 C106.1 C109.1 J3.1(A) J10.1 L1.2 L2.2 L3.2 L4.2 Q6.5(D) R8.1 R10.2 R25.1 R111.1 R114.1
VOUT0_CFG: R30.1 R31.2 U2.18(VOUT0_CFG)
VOUT1_CFG: R33.1 R34.2 U2.19(VOUT1_CFG)
VSENSE0+: E6.1(TP) R10.1 U2.1(VSENSE0+) U2.27(VSENSE1)
VSENSE0-: E7.1(TP) R13.1 U2.2(VSENSE0-)
N25214003: L1.1 R7.1 U1.16(SW) U1.17(SW) U1.18(SW) U1.19(SW) U1.20(SW) U1.21(SW) U1.22(SW) U1.23(SW) U1.24(SW) U1.25(SW) U1.26(SW)
N25214009: C44.1 R24.2 U2.3(ISNS1+)
N25214017: C39.2 C44.2 R25.2 U2.4(ISNS1-)
N25214035: C18.1 R7.2 U2.6(ISNS0+)
N25214110: R3.1 U1.31(EN/FAULT#)
N25214136: R4.1 U1.2(ZCD#)
N25214154: C12.2 R5.1
N25214160: R5.2 U1.5(BOOT)
N25214170: C12.1 U1.7(PHASE)
N25214212: L2.1 R24.1 U3.16(SW) U3.17(SW) U3.18(SW) U3.19(SW) U3.20(SW) U3.21(SW) U3.22(SW) U3.23(SW) U3.24(SW) U3.25(SW) U3.26(SW)
N25214264: R16.1 U3.31(EN/FAULT#)
N25214329: R17.1 U3.2(ZCD#)
N25214339: C34.2 R18.1
N25214345: R18.2 U3.5(BOOT)
N25214355: C34.1 U3.7(PHASE)
N25214395: C27.2 R12.2 U3.30(TMON)
N25214489: C3.2 R1.2 U1.30(TMON)
N25214670: C13.2 C18.2 R8.2 U2.7(ISNS0-)
N25271339: C9.1 R2.2 U2.35(VIN)
N25275079: C24.2 R15.1
N25276080: C32.1 Q2.2(EMITTER) U2.40(TSNS0)
N25276115: C30.1 Q1.2(EMITTER) U2.28(TSNS1)
N25447560: J8.2(CTRL) J9.2(CTRL) R52.1 R64.2 R65.2
N25447562: J8.10(UNUSED) J9.10(UNUSED) R54.2
N25447566: J8.1(FAULTB) J9.1(FAULTB) R49.1
N25447592: R73.2 U5.3(SET)
N25447600: JP3.1 R71.2
N25447602: JP3.2 JP3.3 Q6.4(G) R67.2 R74.1
N25447616: R73.1 R76.1 U5.1(MOD)
N25447637: R69.1 U5.6(OUT)
N25447647: R72.1 R78.1 U5.4(DIV)
N25447700: C53.2 J11.1 Q6.1(S) Q6.2(S) Q6.3(S) R75.2 R80.2
N25447880: C50.2 R75.1 U6.4(-IN)
N25447884: R77.2 R79.3
N25447900: C50.1 R71.1 U6.1(VOUT)
N25447906: R69.2 R77.1 U6.3(+IN)
N25447980: E17.1(TP) R67.1
N25448498: J8.5(SHARE_CLK) J9.5(SHARE_CLK) R55.2
N25448502: J8.7(RESETB) J9.7(RESETB)
N25448508: J8.9(UNUSED) J9.9(UNUSED) R56.2
N25448578: J7.8(OUTEN_0) R64.1
N25448791: J8.13(12V) J8.14(12V) J9.13(12V) J9.14(12V) R62.2
N25448863: J7.9(OUTEN_1) R65.1
N25456892: JP4.2 R70.2 U7.5(~{SHDN})
N25459082: D2.1(CATHODE) Q4.3(D)
N25460507: D5.2(ANODE) Q5.3(D)
N25460530: D5.1(CATHODE) R63.1
N25473428: Q7.1(G) R82.2 R83.1
N25490068: JP5.2 R81.2 U8.5(~{SHDN})
N25553671: C45.1 R58.1
N25694603: C74.1 R93.2 U12.17(VIN)
N25695463: L3.1 R110.1 U10.16(SW) U10.17(SW) U10.18(SW) U10.19(SW) U10.20(SW) U10.21(SW) U10.22(SW) U10.23(SW) U10.24(SW) U10.25(SW) U10.26(SW)
N25695465: C101.1 R113.2 U12.6(ISNS1+)
N25695477: C101.2 C106.2 R114.2 U12.5(ISNS1-)
N25695495: C89.1 R110.2 U12.1(ISNS0+)
N25695531: R121.1 U10.31(EN/FAULT#)
N25695598: R122.1 U10.2(ZCD#)
N25695608: C88.2 R112.1
N25695622: R112.2 U10.5(BOOT)
N25695624: C88.1 U10.7(PHASE)
N25695676: L4.1 R113.1 U11.16(SW) U11.17(SW) U11.18(SW) U11.19(SW) U11.20(SW) U11.21(SW) U11.22(SW) U11.23(SW) U11.24(SW) U11.25(SW) U11.26(SW)
N25695755: R119.1 U11.31(EN/FAULT#)
N25695885: R120.1 U11.2(ZCD#)
N25695919: C100.2 R115.1
N25695925: R115.2 U11.5(BOOT)
N25695949: C100.1 U11.7(PHASE)
N25696007: C102.2 R117.2 U11.30(TMON)
N25696139: C104.2 R118.2 U10.30(TMON)
N25696348: C89.2 C109.2 R111.2 U12.2(ISNS0-)
N25698165: R123.2 U12.22(FREQ)
N25698264: R124.2 R125.2 U12.7(MODE1) U12.24(MODE0)
N25706425: R68.2 R126.1 U12.11(PHASMD)
N25706803: R127.2 R128.1 U12.9(ILIM)
N25722646: D2.2(ANODE) R47.2

Not connected (* = marked no-connect by the designer): J7 7(GPIO_1); JP4 3; JP5 3; SW1 4 5 6; U1 6(NC) 27(GL) 35(GL); U2 29(NC) 32(NC) 36(NC) 39(NC); U3 6(NC) 27(GL) 35(GL); U7 4(NC)*; U8 4(NC)*; U10 6(NC) 27(GL) 35(GL); U11 6(NC) 27(GL) 35(GL)

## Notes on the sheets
sheet 1
- 1210
- 1210
- 1210
- 1210
- 1210
- 1210
- 1210
- 1210
- 1210
- 1210
- 1210
- 1210
sheet 2
- 7V-14V
- 16V
- 16V
- WURTH, 744355215
- 1.0V/100A
- 1210
- 1210
- 1210
- 1210
- 1210
- 1210
- 1210
- 1210
- 1210
- 1210
- WURTH, 744355215
- 1210
- 1210
- NOTE: UNLESS OTHERWISE SPECIFIED
- 1.  ALL RESISTORS ARE IN 0603.
       ALL CAPACITORS ARE IN  0603.
- 2.  INSTALL SHUNTS AS SHOWN.
- AND DIGITAL POWER SYSTEM MANAGEMENT
sheet 3
- GPIO0B
- RUN1
- ON
- TO DC1613A
- OFF
- ALERTB
- 1206
- C
- GPIO0-GPIO1
- NC
- VOUT0
- INT / EXT PULSE
- DrMOS
- VDR
- INT
- EXT
- 70Hz, 3% Duty Cycle
- ON
- IOUT
  TST
- OFF
- 1%
- 0805
- LOAD
- STEP
- PULSE
- GENERATOR
- ON
- OFF
